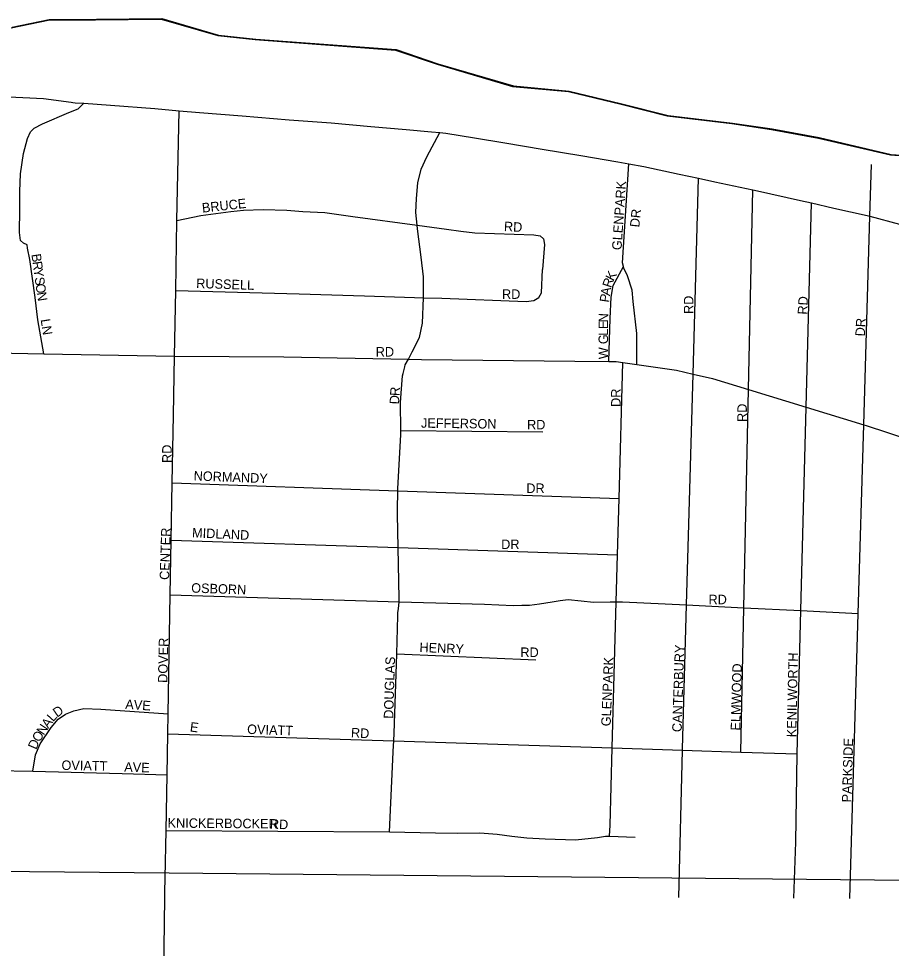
# Model space of a CAD drawing. Extents: x -561 to 1170, y 0 to 846.
# Drawn here: x 71.76 to 84.16, y 265 to 278.2 of the extents above; entities that cross this region are included whole.
import ezdxf

# ---------------------------------------------------------------- set-up
doc = ezdxf.new("R2010")
doc.units = 0
for name, color, linetype in [('GM_X_City_Street', 7, 'Continuous'), ('GM_X_City_Street_Text', 7, 'Continuous'), ('GM_X_County', 7, 'Continuous'), ('GM_X_Major_Lake', 7, 'Continuous'), ('GM_X_Major_River', 7, 'Continuous'), ('GM_X_Rail_Line', 7, 'Continuous'), ('GM_X_US_Route', 7, 'Continuous')]:
    doc.layers.add(name, color=color, linetype=linetype)

msp = doc.modelspace()

# ---------------------------------------------------------------- linework, layer by layer
at = {"layer": 'GM_X_City_Street'}
for points in [[(72.12, 273.444), (72.034, 273.924), (71.998, 274.243), (71.923, 274.784), (71.889, 274.941), (71.883, 274.989), (71.834, 275.016), (71.79, 275.053), (71.773, 275.167), (71.78, 275.492), (71.778, 275.747), (71.791, 276.001), (71.832, 276.289), (71.889, 276.501), (71.932, 276.593), (71.985, 276.648), (72.104, 276.709), (72.476, 276.87), (72.611, 276.92), (72.689, 277.001)], [(73.846, 266.002), (73.858, 266.674), (73.872, 267.464), (73.882, 268.049), (73.887, 268.33), (73.917, 270.02), (73.931, 270.799), (73.946, 271.611), (73.963, 272.572), (73.978, 273.408), (73.995, 274.344), (74.013, 275.338), (74.042, 276.895)], [(77.228, 273.164), (77.251, 273.259), (77.257, 273.285), (77.301, 273.367), (77.356, 273.469), (77.459, 273.674), (77.503, 273.88), (77.514, 274.239), (77.516, 274.291), (77.517, 274.535), (77.481, 274.816), (77.428, 275.217), (77.424, 275.27), (77.408, 275.45), (77.414, 275.65), (77.437, 275.872), (77.481, 276.067), (77.563, 276.24), (77.747, 276.584)], [(80.549, 273.292), (80.546, 273.732), (80.494, 274.187), (80.479, 274.349), (80.415, 274.55), (80.361, 274.658), (80.356, 274.684), (80.345, 274.734), (80.434, 276.14)], [(83.573, 265.707), (83.69, 269.757), (83.77, 272.434), (83.859, 275.399), (83.881, 276.132)], [(81.142, 265.723), (81.194, 267.815), (81.195, 267.829), (81.252, 269.877), (81.345, 273.156), (81.423, 275.936)], [(82.026, 267.788), (82.069, 269.837), (82.134, 272.935), (82.193, 275.771)], [(82.778, 265.714), (82.805, 266.507), (82.827, 267.763), (82.879, 269.797), (82.954, 272.684), (83.029, 275.585)], [(74.013, 275.338), (74.352, 275.405), (74.779, 275.464), (74.958, 275.482), (75.239, 275.49), (75.574, 275.483), (75.802, 275.463), (76.116, 275.45), (76.512, 275.395), (77.424, 275.27), (77.84, 275.214), (78.046, 275.183), (78.246, 275.163), (79.085, 275.134), (79.172, 275.119), (79.221, 275.076), (79.233, 274.995), (79.204, 274.642)], [(73.995, 274.344), (75.748, 274.293), (76.678, 274.268), (77.389, 274.244), (77.514, 274.239), (77.775, 274.231), (78.975, 274.188), (79.083, 274.198), (79.154, 274.241), (79.192, 274.311), (79.204, 274.642)], [(80.149, 273.335), (80.169, 273.945), (80.181, 274.248), (80.209, 274.415), (80.356, 274.684)], [(70.753, 273.47), (72.12, 273.444), (73.978, 273.408)], [(73.978, 273.408), (75.533, 273.399), (77.301, 273.367), (77.489, 273.364), (79.666, 273.339), (80.149, 273.335), (80.255, 273.334), (80.349, 273.321), (80.549, 273.292), (81.109, 273.211), (81.345, 273.156), (81.622, 273.092), (82.134, 272.935), (82.954, 272.684), (83.77, 272.434), (83.805, 272.424), (84.741, 272.118)], [(80.157, 266.592), (80.168, 266.751), (80.198, 267.847), (80.255, 269.922), (80.274, 270.588), (80.296, 271.389), (80.349, 273.321)], [(77.148, 271.326), (77.15, 271.399), (77.152, 271.499), (77.152, 271.527), (77.193, 272.295), (77.193, 272.355), (77.19, 272.75), (77.202, 272.945), (77.219, 273.129), (77.228, 273.164)], [(77.193, 272.355), (79.21, 272.335)], [(73.946, 271.611), (77.152, 271.499), (80.296, 271.389)], [(77.153, 269.769), (77.159, 269.824), (77.168, 269.923), (77.172, 269.967), (77.156, 270.692), (77.145, 271.159), (77.148, 271.326)], [(73.931, 270.799), (77.156, 270.692), (80.274, 270.588)], [(73.917, 270.02), (77.168, 269.923), (78.382, 269.887), (78.788, 269.869), (78.912, 269.874), (79.02, 269.873), (79.166, 269.894), (79.345, 269.921), (79.458, 269.942), (79.572, 269.952), (79.756, 269.935), (79.929, 269.918), (80.166, 269.923), (80.255, 269.922), (80.29, 269.922), (80.307, 269.922)], [(80.307, 269.922), (80.345, 269.922), (81.252, 269.877), (82.069, 269.837), (82.879, 269.797), (83.69, 269.757)], [(77.086, 267.787), (77.086, 267.799), (77.093, 267.946), (77.098, 268.057), (77.129, 268.896), (77.136, 269.183), (77.149, 269.724), (77.153, 269.769)], [(77.136, 269.183), (79.114, 269.099)], [(71.966, 267.517), (72.005, 267.748), (72.071, 267.905), (72.223, 268.137), (72.326, 268.255), (72.429, 268.325), (72.549, 268.374), (72.689, 268.405), (72.932, 268.399), (73.887, 268.33)], [(73.882, 268.049), (77.093, 267.946), (80.198, 267.847), (81.194, 267.815), (82.026, 267.788), (82.827, 267.763)], [(77.033, 266.655), (77.086, 267.787)], [(70.807, 267.711), (70.999, 267.611), (71.134, 267.557), (71.426, 267.528), (71.966, 267.517), (73.236, 267.483), (73.872, 267.464)], [(73.858, 266.674), (77.033, 266.655), (77.687, 266.642), (78.005, 266.635), (78.314, 266.639), (78.562, 266.622), (78.773, 266.594), (78.984, 266.571), (79.243, 266.554), (79.675, 266.541), (79.989, 266.573), (80.102, 266.594), (80.157, 266.592), (80.524, 266.581)], [(73.841, 265.717), (73.842, 265.797), (73.846, 266.002)], [(73.819, 264.293), (73.841, 265.717)]]:
    msp.add_lwpolyline(points, dxfattribs=at)
at = {"layer": 'GM_X_County'}
msp.add_lwpolyline([(71.659, 278.072), (72.184, 278.183), (72.856, 278.186), (73.788, 278.196), (74.591, 277.962), (75.122, 277.905), (77.116, 277.757), (77.708, 277.554), (78.782, 277.239), (79.574, 277.167), (80.322, 276.987), (80.978, 276.822), (81.895, 276.713), (82.459, 276.629), (83.126, 276.507), (84.151, 276.268), (84.714, 276.228)], dxfattribs=at)
at = {"layer": 'GM_X_Major_Lake'}
msp.add_lwpolyline([(71.67, 278.079), (72.195, 278.19), (72.867, 278.193), (73.799, 278.203), (74.602, 277.968), (75.133, 277.911), (77.128, 277.764), (77.719, 277.561), (78.794, 277.246), (79.585, 277.174), (80.334, 276.994), (80.99, 276.829), (81.906, 276.72), (82.47, 276.636), (83.137, 276.514), (84.162, 276.275), (84.726, 276.235)], dxfattribs=at)
msp.add_lwpolyline([(71.67, 278.079), (72.195, 278.19), (72.867, 278.193), (73.799, 278.203), (74.602, 277.968), (75.133, 277.911), (77.128, 277.764), (77.719, 277.561), (78.794, 277.246), (79.585, 277.174), (80.334, 276.994), (80.99, 276.829), (81.906, 276.72), (82.47, 276.636), (83.137, 276.514), (84.162, 276.275), (84.726, 276.235)], dxfattribs=at)
at = {"layer": 'GM_X_Major_River'}
msp.add_lwpolyline([(71.67, 278.079), (72.195, 278.19), (72.867, 278.193), (73.799, 278.203), (74.602, 277.968), (75.133, 277.911), (77.128, 277.764), (77.719, 277.561), (78.794, 277.246), (79.585, 277.174), (80.334, 276.994), (80.99, 276.829), (81.906, 276.72), (82.47, 276.636), (83.137, 276.514), (84.162, 276.275), (84.726, 276.235)], dxfattribs=at)
at = {"layer": 'GM_X_Rail_Line'}
msp.add_lwpolyline([(38.104, 266.374), (46.926, 266.33), (48.807, 266.32), (50.698, 266.304), (52.237, 266.285), (56.506, 266.247), (59.789, 266.214), (63.592, 266.177), (68.925, 266.123), (70.922, 266.1), (73.902, 266.071), (82.475, 265.99), (88.766, 265.928)], dxfattribs=at)
at = {"layer": 'GM_X_US_Route'}
for points in [[(69.988, 277.194), (70.411, 277.177), (70.725, 277.172), (71.104, 277.139), (71.531, 277.096), (72.115, 277.069), (72.508, 277.017), (72.533, 277.013)], [(72.533, 277.013), (72.564, 277.009), (72.689, 277.001), (73.067, 276.976), (73.7, 276.928), (74.042, 276.895), (74.333, 276.868), (74.938, 276.824), (75.609, 276.765), (76.204, 276.721), (76.767, 276.672), (77.27, 276.629), (77.627, 276.596), (77.747, 276.584), (77.832, 276.575), (78.238, 276.51), (78.67, 276.439), (79.201, 276.347), (79.752, 276.26), (80.277, 276.168), (80.434, 276.14), (80.645, 276.103), (81.148, 275.995), (81.423, 275.936), (81.656, 275.886), (82.193, 275.771), (82.262, 275.756), (82.873, 275.621), (83.029, 275.585), (83.344, 275.512), (83.819, 275.409), (83.859, 275.399), (84.279, 275.285)]]:
    msp.add_lwpolyline(points, dxfattribs=at)

# ---------------------------------------------------------------- texts
at = {"layer": 'GM_X_City_Street_Text'}
for s, rotation, p in [('GLENPARK', 86.1352, (80.328, 274.912)), ('BRUCE', 6.2051, (74.375, 275.447)), ('DR', 83.9889, (80.581, 275.234)), ('RD', 356.9887, (78.656, 275.186)), ('B', 277.8691, (71.944, 274.855)), ('R', 277.8734, (71.959, 274.749)), ('Y', 277.8839, (71.973, 274.643)), ('K', 62.389, (80.213, 274.467)), ('S', 277.8673, (71.99, 274.525)), ('RUSSELL', 358.0919, (74.284, 274.378)), ('R', 70.9621, (80.18, 274.371)), ('O', 277.8682, (72.003, 274.431)), ('RD', 0, (78.631, 274.223)), ('A', 81.5654, (80.164, 274.26)), ('N', 279.2639, (72.019, 274.31)), ('P', 81.5665, (80.15, 274.166)), ('RD', 90, (81.35, 274.008)), ('RD', 86.989, (82.966, 273.997)), ('N', 88.2947, (80.138, 273.888)), ('LN', 278.9673, (72.075, 273.929)), ('E', 89.959, (80.138, 273.794)), ('DR', 86.989, (83.785, 273.688)), ('G', 89.9563, (80.138, 273.58)), ('L', 89.959, (80.138, 273.699)), ('RD', 0, (76.837, 273.404)), ('W', 90, (80.138, 273.366)), ('R', 86.6585, (77.174, 272.841)), ('DR', 90, (80.316, 272.689)), ('D', 87.322, (77.168, 272.723)), ('RD', 90, (82.11, 272.475)), ('JEFFERSON', 359.2365, (77.479, 272.394)), ('RD', 0, (78.987, 272.37)), ('RD', 90, (73.937, 271.893)), ('NORMANDY', 357.9059, (74.248, 271.645)), ('DR', 0, (78.976, 271.467)), ('CENTER', 88.2094, (73.901, 270.231)), ('MIDLAND', 357.3989, (74.225, 270.837)), ('DR', 0, (78.619, 270.671)), ('OSBORN', 357.9557, (74.213, 270.053)), ('RD', 0, (81.565, 269.887)), ('DOVER', 88.8072, (73.877, 268.769)), ('HENRY', 357.6107, (77.456, 269.209)), ('RD', 0, (78.892, 269.138)), ('CANTERBURY', 88.1719, (81.183, 268.069)), ('DOUGLAS', 88.2635, (77.085, 268.259)), ('GLENPARK', 87.6783, (80.174, 268.152)), ('KENILWORTH', 88.7675, (82.811, 267.997)), ('ELMWOOD', 88.4315, (82.015, 268.092)), ('D', 34.8479, (72.309, 268.275)), ('AVE', 356.0571, (73.275, 268.402)), ('L', 48.1021, (72.252, 268.21)), ('N', 56.507, (72.119, 268.019)), ('A', 53.8601, (72.184, 268.116)), ('E', 352.88, (74.191, 268.081)), ('OVIATT', 358.1499, (75.008, 268.046)), ('O', 58.5228, (72.058, 267.918)), ('RD', 356.9887, (76.482, 267.998)), ('D', 66.711, (72.013, 267.814)), ('PARKSIDE', 88.3146, (83.595, 267.071)), ('OVIATT', 358.8989, (72.371, 267.535)), ('AVE', 358.0261, (73.262, 267.511)), ('KNICKERBOCKER', 359.5129, (73.879, 266.715)), ('RD', 356.989, (75.33, 266.703))]:
    msp.add_text(s, height=0.135, rotation=rotation, dxfattribs=at).set_placement(p)

doc.saveas('drawing.dxf')
